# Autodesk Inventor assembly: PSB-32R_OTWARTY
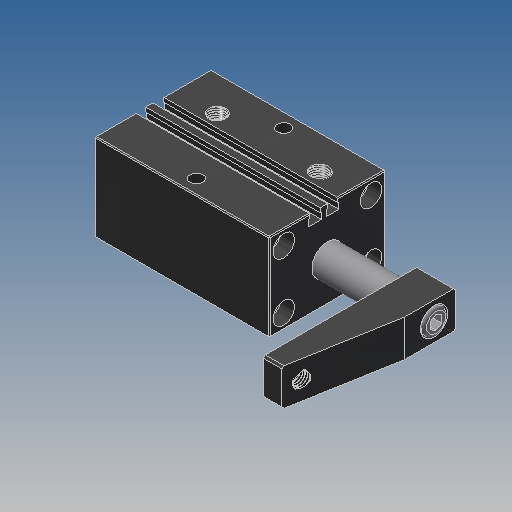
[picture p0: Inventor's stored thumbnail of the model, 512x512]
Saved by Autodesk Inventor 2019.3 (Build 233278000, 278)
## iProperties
Created: 2010-02
Part Number: PSB-32R_OTWARTY
Material: Ogólny
Document SubType Name: Assembly
Designer: CADENGINEERING4
Sending System: PRO/ENGINEER BY PARAMETRIC TECHNOLOGY CORPORATION, 2007170
Preprocessor: PRO/ENGINEER BY PARAMETRIC TECHNOLOGY CORPORATION, 2007170
Title: PSB-32_ASM
Author: Administrator
Revision Number: 1LAST_VERSION
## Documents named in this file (6)
- E:\SERWER_ZAPAS\Pneumatic\PSB PNEUMATIC SWING\PSB-32\PSB-32R_OTWARTY.iam
- E:\SERWER_ZAPAS\Pneumatic\PSB PNEUMATIC SWING\PSB-32\PSB-32BT.ipt
- E:\SERWER_ZAPAS\Pneumatic\PSB PNEUMATIC SWING\PSB-32\PSB-32HSG.ipt
- E:\SERWER_ZAPAS\Pneumatic\PSB PNEUMATIC SWING\PSB-32\PSB-32HG.ipt
- E:\SERWER_ZAPAS\Pneumatic\PSB PNEUMATIC SWING\PSB-32\PSB-32YB.ipt
- E:\SERWER_ZAPAS\Pneumatic\PSB PNEUMATIC SWING\PSB-32\M8X20.ipt
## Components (5 placed, 5 different names)
1. PSB-32BT_0 — Zestawiające:1, Zestawiające:6, Kątowe:1
2. PSB-32HSG_1 — Zestawiające:1, Zestawiające:2, Zestawiające:3, Zestawiające:6
3. PSB-32HG_2
4. PSB-32YB_3 — Zestawiające:2, Zestawiające:3, Zestawiające:4, Zestawiające:5, Kątowe:1
5. M8X20_4 — Zestawiające:4, Zestawiające:5
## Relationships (7: Mate 6, Angle 1)
- Zestawiające:1 [Mate]: PSB-32BT_0 ↔ PSB-32HSG_1
- Zestawiające:2 [Mate]: PSB-32HSG_1 ↔ PSB-32YB_3
- Zestawiające:3 [Mate]: PSB-32HSG_1 ↔ PSB-32YB_3
- Zestawiające:4 [Mate]: PSB-32YB_3 ↔ M8X20_4
- Zestawiające:5 [Mate]: PSB-32YB_3 ↔ M8X20_4
- Zestawiające:6 [Mate]: PSB-32BT_0 ↔ PSB-32HSG_1
- Kątowe:1 [Angle]: PSB-32BT_0 ↔ PSB-32YB_3
